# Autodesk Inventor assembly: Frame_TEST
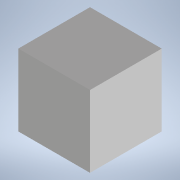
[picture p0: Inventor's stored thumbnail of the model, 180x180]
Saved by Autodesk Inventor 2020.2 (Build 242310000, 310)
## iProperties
Created: 2020-01
Part Number: Frame_TEST
Document SubType Name: Assembly
Designer: thira
Author: thira
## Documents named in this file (2)
- C:\Users\thira\OneDrive\เดสก์ท็อป\INV-01 Intro to Modeling_2020\FRAME\Frame_TEST.iam
- C:\Users\thira\OneDrive\เดสก์ท็อป\INV-01 Intro to Modeling_2020\FRAME\Structure.ipt
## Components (1 placed, 1 different names)
1. Structure:1
